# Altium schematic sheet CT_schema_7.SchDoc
size 277 x 170 mm
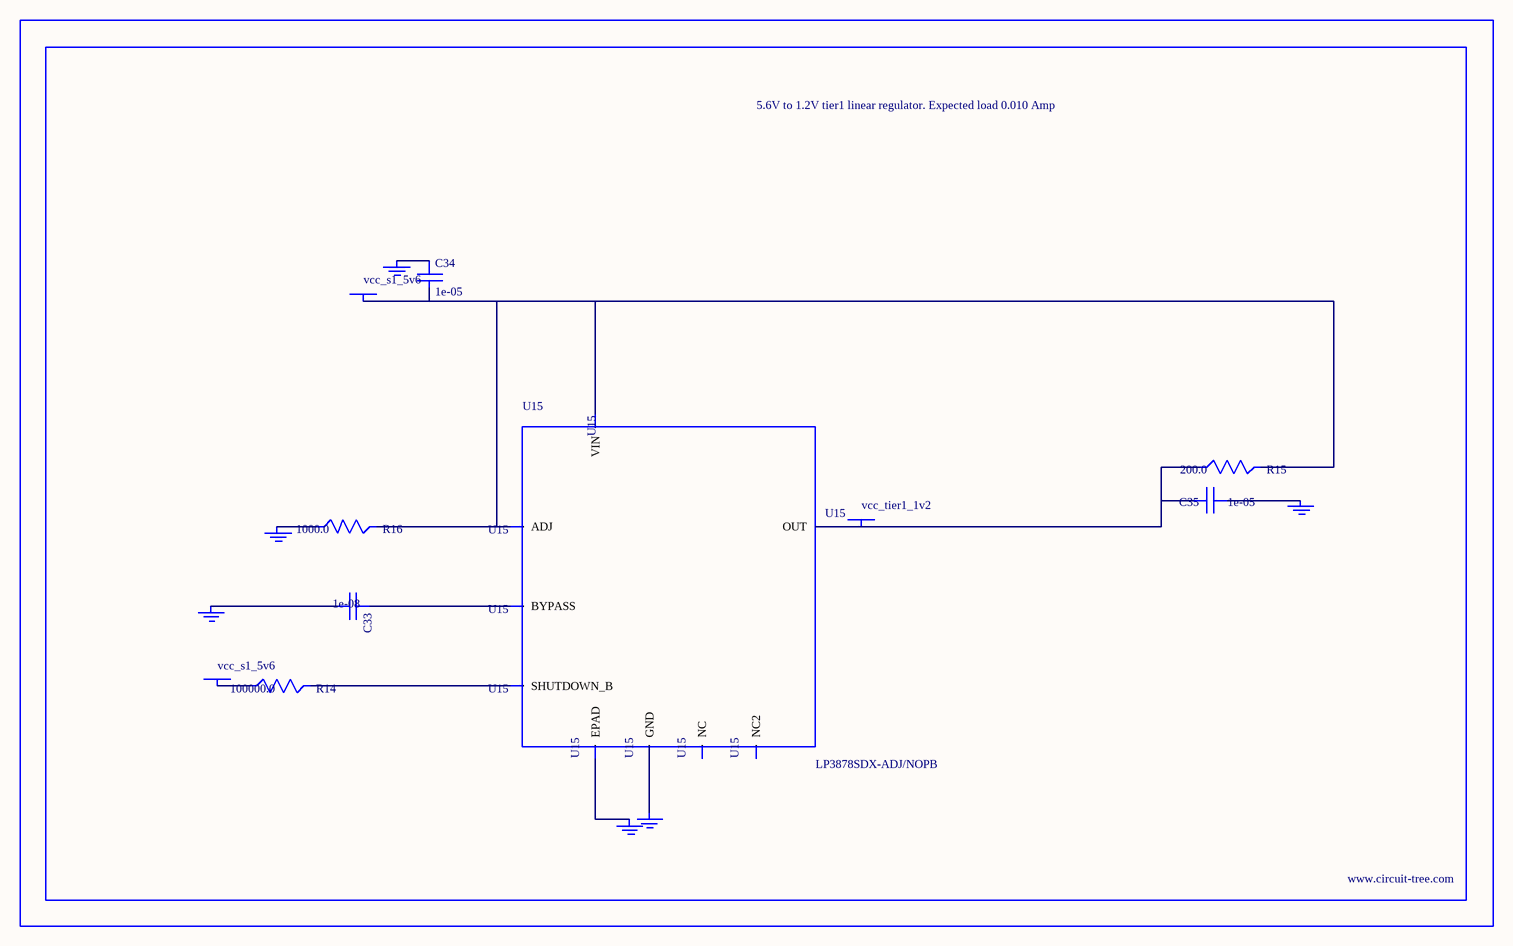
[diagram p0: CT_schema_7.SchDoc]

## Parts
BORDER6  (no value)
C33  1e-08  [C0402]
C34  1e-05  [C1206]
C35  1e-05  [C0805]
GND_INSTANCE_6_0  (no value)
GND_INSTANCE_6_1  (no value)
GND_INSTANCE_6_2  (no value)
GND_INSTANCE_6_3  (no value)
GND_INSTANCE_6_4  (no value)
GND_INSTANCE_6_5  (no value)
POWER_INSTANCE_6_0  vcc_s1_5v6
POWER_INSTANCE_6_1  vcc_s1_5v6
POWER_INSTANCE_6_2  vcc_tier1_1v2
R14  100000.0  [R0603]
R15  200.0  [R0603]
R16  1000.0  [R0603]
U15  LP3878SDX-ADJ/NOPB  [WSON-8]

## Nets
NetC33_1: C33.1 U15.1(BYPASS)
NetC33_2: C33.2 GND_INSTANCE_6_0.0(GND)
NetC34_1: C34.1 GND_INSTANCE_6_1.0(GND)
NetC34_2: C34.2 POWER_INSTANCE_6_0.0(PWR) R15.2 R16.2 U15.4(VIN) U15.6(ADJ)
NetC35_1: C35.1 GND_INSTANCE_6_2.0(GND)
NetC35_2: C35.2 POWER_INSTANCE_6_2.0(PWR) R15.1 U15.5(OUT)
NetGND_INSTANCE_6_3_0: GND_INSTANCE_6_3.0(GND) R16.1
NetGND_INSTANCE_6_4_0: GND_INSTANCE_6_4.0(GND) U15.PAD(EPAD)
NetGND_INSTANCE_6_5_0: GND_INSTANCE_6_5.0(GND) U15.3(GND)
NetPOWER_INSTANCE_6_1_0: POWER_INSTANCE_6_1.0(PWR) R14.1
NetR14_2: R14.2 U15.8(SHUTDOWN_B)

Not connected (* = marked no-connect by the designer): U15 2(NC) 7(NC2)

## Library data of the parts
BORDER6 = BORDER_PAGE6
C33 = C0402C103K3RAC
C34 = C1206C106K3RACTU
C35 = GRM219R60J106ME19D
GND_INSTANCE_6_0-GND_INSTANCE_6_5 = GND
POWER_INSTANCE_6_0-POWER_INSTANCE_6_2 = PWR
R14 = RC0603JR-07100KL
R15 = RC0603JR-07200RL
R16 = RC0603JR-071KL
